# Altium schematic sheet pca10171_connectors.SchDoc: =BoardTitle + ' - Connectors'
size A3; Organization: Nordic Semiconductor; DocumentNumber: 7; SheetNumber: 7; SheetTotal: 10; CompanyName: Nordic Semiconductor; DocumentSize: A3
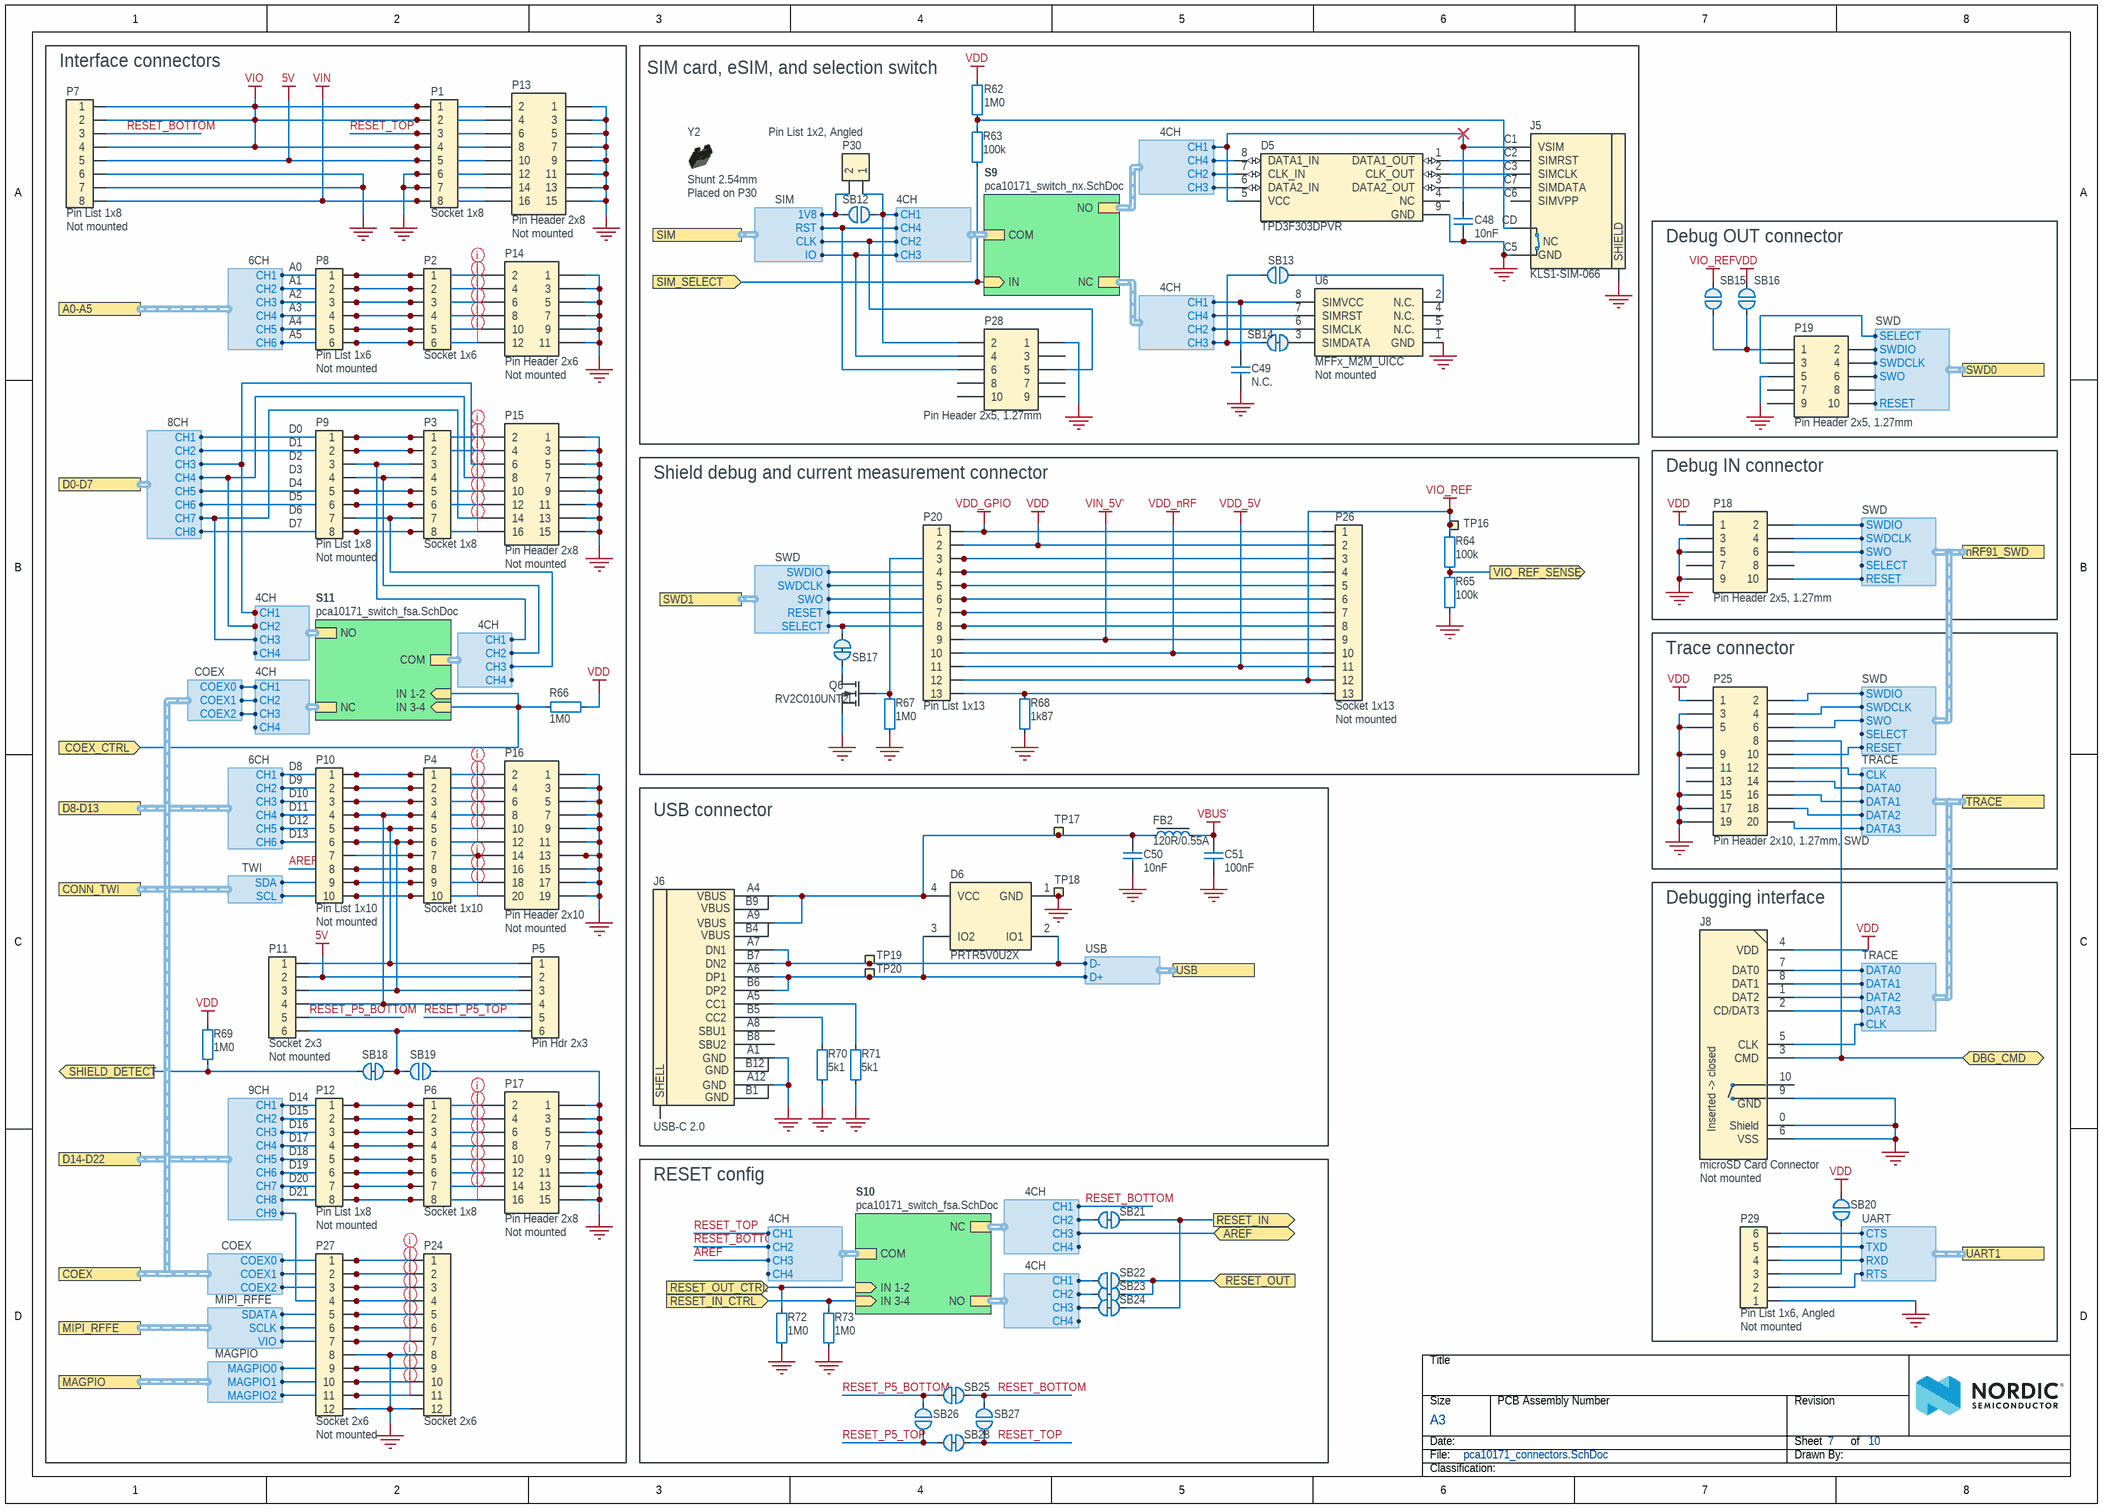
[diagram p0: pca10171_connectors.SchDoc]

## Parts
C48  10nF  [CAPC0603X03L_C]
C49  N.C.  [CAPC0603X03L_C_NC]
C50  10nF  [CAPC0603X03L_C]
C51  100nF  [CAPC0603X03L_C]
D5  TPD3F303DPVR  [SON50P210X160X65_HS-9N]
D6  PRTR5V0U2X  [SOT190P230X110-4L]
FB2  120R/0.55A  [INDC1005X04L]
J5  KLS1-SIM-066  [KLS1-SIM-066]
J6  USB-C 2.0  [SD-80259-001]
J8  microSD Card Connector  Assembly: Not mounted  [Molex_502774-0891]
P1  Socket 1x8  [SOCKET_1x8_SMD]
P2  Socket 1x6  [SOCKET_1x6_SMD]
P3  Socket 1x8  [SOCKET_1x8_SMD]
P4  Socket 1x10  [SOCKET_1x10_SMD]
P5  Pin Hdr 2x3  [HDR_2x3-SMD]
P6  Socket 1x8  [SOCKET_1x8_SMD]
P7  Pin List 1x8  Assembly: Not mounted  [LIST_1x8_SMD-NC]
P8  Pin List 1x6  Assembly: Not mounted  [LIST_1x6_SMD-NC]
P9  Pin List 1x8  Assembly: Not mounted  [LIST_1x8_SMD-NC]
P10  Pin List 1x10  Assembly: Not mounted  [LIST_1x10_SMD-NC]
P11  Socket 2x3  Assembly: Not mounted  [SOCKET_2x3_SMD-2.54mm-bottom-NC]
P12  Pin List 1x8  Assembly: Not mounted  [LIST_1x8_SMD-NC]
P13  Pin Header 2x8  Assembly: Not mounted  [HDR_2x8-NC]
P14  Pin Header 2x6  Assembly: Not mounted  [HDR_2x6-NC]
P15  Pin Header 2x8  Assembly: Not mounted  [HDR_2x8-NC]
P16  Pin Header 2x10  Assembly: Not mounted  [HDR_2x10-NC]
P17  Pin Header 2x8  Assembly: Not mounted  [HDR_2x8-NC]
P18  Pin Header 2x5, 1.27mm  [HDR_2x5-SMD-1.27mm-K]
P19  Pin Header 2x5, 1.27mm  [HDR_2x5-SMD-1.27mm-K]
P20  Pin List 1x13  [LIST_1x13_SMD]
P24  Socket 2x6  [SOCKET_2x6_SMD-2.54mm]
P25  Pin Header 2x10, 1.27mm, SWD  [HDR_2x10-SMD-1.27mm-K-SWD]
P26  Socket 1x13  Assembly: Not mounted  [LIST_1x13_SMD-NC]
P27  Socket 2x6  Assembly: Not mounted  [SOCKET_2x6_SMD-2.54mm]
P28  Pin Header 2x5, 1.27mm  [HDR_2x5-SMD-1.27mm]
P29  Pin List 1x6, Angled  Assembly: Not mounted  [LIST_ANG_1x6-SMD-2.54MM]
P30  Pin List 1x2, Angled  [LIST_ANG_1x2-SMD-2.54MM]
Q6  RV2C010UNT2L  [DFN65P100X40-3L]
R62  1M0  [RESC0603X03L_C]
R63  100k  [RESC0603X03L_C]
R64  100k  [RESC0603X03L_C]
R65  100k  [RESC0603X03L_C]
R66  1M0  [RESC0603X03L_C]
R67  1M0  [RESC0603X03L_C]
R68  1k87  [RESC0603X03L_C]
R69  1M0  [RESC0603X03L_C]
R70  5k1  [RESC0603X03L_C]
R71  5k1  [RESC0603X03L_C]
R72  1M0  [RESC0603X03L_C]
R73  1M0  [RESC0603X03L_C]
SB12  Solderbridge  [Solderbridge]  (value not drawn)  (no BOM)
SB13  Solderbridge  [Solderbridge]  (value not drawn)  (no BOM)
SB14  Solderbridge  [Solderbridge_Shorted]  (value not drawn)  (net tie, no BOM)
SB15  Solderbridge  [Solderbridge]  (value not drawn)  (no BOM)
SB16  Solderbridge  [Solderbridge]  (value not drawn)  (no BOM)
SB17  Solderbridge  [Solderbridge_Shorted]  (value not drawn)  (net tie, no BOM)
SB18  Solderbridge  [Solderbridge_Shorted]  (value not drawn)  (net tie, no BOM)
SB19  Solderbridge  [Solderbridge]  (value not drawn)  (no BOM)
SB20  Solderbridge  [Solderbridge]  (value not drawn)  (no BOM)
SB21  Solderbridge  [Solderbridge_Shorted]  (value not drawn)  (net tie, no BOM)
SB22  Solderbridge  [Solderbridge]  (value not drawn)  (no BOM)
SB23  Solderbridge  [Solderbridge_Shorted]  (value not drawn)  (net tie, no BOM)
SB24  Solderbridge  [Solderbridge_Shorted]  (value not drawn)  (net tie, no BOM)
SB25  Solderbridge  [Solderbridge_Shorted]  (value not drawn)  (net tie, no BOM)
SB26  Solderbridge  [Solderbridge]  (value not drawn)  (no BOM)
SB27  Solderbridge  [Solderbridge]  (value not drawn)  (no BOM)
SB28  Solderbridge  [Solderbridge_Shorted]  (value not drawn)  (net tie, no BOM)
TP16  Ø1.5mm,SMD  [TP_SMD_D1.5mm]  (value not drawn)  (no BOM)
TP17  Ø1.5mm,SMD  [TP_SMD_D1.5mm]  (value not drawn)  (no BOM)
TP18  Ø1.5mm,SMD  [TP_SMD_D1.5mm]  (value not drawn)  (no BOM)
TP19  Ø1.5mm,SMD  [TP_SMD_D1.5mm]  (value not drawn)  (no BOM)
TP20  Ø1.5mm,SMD  [TP_SMD_D1.5mm]  (value not drawn)  (no BOM)
U6  MFFx_M2M_UICC  Assembly: Not mounted  [SON127P600X90_HS-8N]
Y2  Shunt 2.54mm  Assembly: Placed on P30  [Shunt_2.54mm_Horizontal]

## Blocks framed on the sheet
Interface connectors: P1-P17 P24 P27 R66 R69 SB18 SB19
SIM card, eSIM, and selection switch: C48 C49 D5 J5 P28 P30 R62 R63 SB12-SB14 U6 Y2
Debug OUT connector: P19 SB15 SB16
Debug IN connector: P18
Shield debug and current measurement connector: P20 P26 Q6 R64 R65 R67 R68 SB17 TP16
Trace connector: P25
USB connector: C50 C51 D6 FB2 J6 R70 R71 TP17-TP20
Debugging interface: J8 P29 SB20
RESET config: R72 R73 SB21-SB28

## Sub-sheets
S9 = pca10171_switch_nx.SchDoc: IN (in), COM (harness 4CH), NC (harness 4CH), NO (harness 4CH)
S10 = pca10171_switch_fsa.SchDoc: IN 1-2 (in), COM (harness 4CH), NC (harness 4CH), NO (harness 4CH), IN 3-4 (in)
S11 = pca10171_switch_fsa.SchDoc: IN 1-2 (in), COM (harness 4CH), NC (harness 4CH), NO (harness 4CH), IN 3-4 (in)

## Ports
A0-A5 (harness 6CH), AREF (bidir), COEX (harness COEX), COEX_CTRL (in), CONN_TWI (harness TWI), D0-D7 (harness 8CH), D8-D13 (harness 6CH), D14-D22 (harness 9CH), DBG_CMD (bidir), MAGPIO (harness MAGPIO), MIPI_RFFE (harness MIPI_RFFE), nRF91_SWD (harness SWD), RESET_IN (out), RESET_IN_CTRL (in), RESET_OUT (in), RESET_OUT_CTRL (in), SHIELD_DETECT (out), SIM (harness SIM), SIM_SELECT (in), SWD0 (harness SWD), SWD1 (harness SWD), TRACE (harness TRACE), UART1 (harness UART), USB (harness USB), VIO_REF_SENSE (out)

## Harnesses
SWD: SWDIO, SWDCLK, SWO, RESET, SELECT
6CH: CH1, CH2, CH3, CH4, CH5, CH6
8CH: CH1, CH2, CH3, CH4, CH5, CH6, CH7, CH8
COEX: COEX0, COEX2, COEX1
TRACE: CLK, DATA0, DATA1, DATA3, DATA2
USB: D+, D-
UART: RTS, CTS, RXD, TXD
MIPI_RFFE: SDATA, VIO, SCLK
MAGPIO: MAGPIO0, MAGPIO2, MAGPIO1
TWI: SCL, SDA
9CH: CH1, CH2, CH3, CH4, CH5, CH6, CH7, CH8, CH9
4CH: CH1, CH2, CH3, CH4
SIM: CLK, IO, 1V8, RST

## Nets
5V: P1.5 P5.2 P7.5 P11.2 P13.10
GND: C48.2 C49.1 C50.1 C51.1 D5.9(GND) D6.1(GND) J5.0(SHIELD) J5.C5(GND) J6.A1(GND) J6.A12(GND) J8.0(Shield) J8.6(VSS) J8.9 P1.6 P1.7 P4.7 P7.6 P7.7 P10.7 P13.1 P13.3 P13.5 P13.7 P13.9 P13.11 P13.12 P13.13 P13.14 P13.15 P14.1 P14.3 P14.5 P14.7 P14.9 P14.11 P15.1 P15.3 P15.5 P15.7 P15.9 P15.11 P15.13 P15.15 P16.1 P16.3 P16.5 P16.7 P16.9 P16.11 P16.13 P16.14 P16.15 P16.17 P16.19 P17.1 P17.3 P17.5 P17.7 P17.9 P17.11 P17.13 P17.15 P18.3 P18.5 P18.9 P19.5 P24.8 P24.12 P25.3 P25.5 P25.9 P25.15 P25.17 P25.19 P27.8 P27.12 P28.1 P29.1 Q6.2(S) R65.1 R67.2 R68.1 R70.1 R71.1 R72.2 R73.1 SB19.1 TP18.1 U6.1(GND)
VBUS': C51.2 FB2.2
VDD: J8.4(VDD) P18.1 P20.2 P25.1 P26.2 R62.1 R66.1 R69.2 SB16.2 SB20.1
VDD_5V: P20.11 P26.11
VDD_GPIO: P20.1 P26.1
VDD_nRF: P20.10 P26.10
VIN: P1.8 P7.8 P13.16
VIN_5V': P20.9 P26.9
VIO: P1.1 P1.2 P1.4 P7.1 P7.2 P7.4 P13.2 P13.4 P13.8
VIO_REF: P20.12 P26.12 R64.1 SB15.2 TP16.1
AREF: P4.8 P10.8 P16.16 ; sheet S10/COM.CH3
AREF: port AREF, sheet S10/NC.CH3  [a separate net that carries the same name]
COEX_CTRL: R66.2 ; port COEX_CTRL, sheet S11/IN 1-2, sheet S11/IN 3-4
DBG_CMD: J8.3(CMD) P25.8 ; port DBG_CMD
RESET_BOTTOM: P7.3 SB25.1 SB27.1 ; sheet S10/NC.CH1, sheet S10/COM.CH2
RESET_IN: SB21.2 SB24.2 ; port RESET_IN
RESET_IN_CTRL: R73.2 ; port RESET_IN_CTRL, sheet S10/IN 3-4
RESET_OUT: SB22.1 SB23.1 ; port RESET_OUT
RESET_OUT_CTRL: R72.1 ; port RESET_OUT_CTRL, sheet S10/IN 1-2
RESET_P5_BOTTOM: P11.5 SB25.2 SB26.2
RESET_P5_TOP: P5.5 SB26.1 SB28.2
RESET_TOP: P1.3 P13.6 SB27.2 SB28.1 ; sheet S10/COM.CH1
SHIELD_DETECT: R69.1 SB18.2 ; port SHIELD_DETECT
SIM_SELECT: R63.1 ; port SIM_SELECT, sheet S9/IN
VIO_REF_SENSE: R64.2 R65.2 ; port VIO_REF_SENSE
NetC48_1: C48.1 D5.5(VCC) J5.C1(VSIM) ; sheet S9/NO.CH1
NetC49_2: C49.2 U6.8(SIMVCC) ; sheet S9/NC.CH1
NetC50_2: C50.2 D6.4(VCC) FB2.1 J6.A4(VBUS) J6.A9(VBUS) TP17.1
NetD5_1: D5.1(DATA1_OUT) J5.C2(SIMRST)
NetD5_2: D5.2(CLK_OUT) J5.C3(SIMCLK)
NetD5_3: D5.3(DATA2_OUT) J5.C7(SIMDATA)
NetD5_6: D5.6(DATA2_IN) ; sheet S9/NO.CH3
NetD5_7: D5.7(CLK_IN) ; sheet S9/NO.CH2
NetD5_8: D5.8(DATA1_IN) ; sheet S9/NO.CH4
NetD6_2: D6.2(IO1) J6.A7(DN1) J6.B7(DN2) TP19.1 ; port USB.D-
NetD6_3: D6.3(IO2) J6.A6(DP1) J6.B6(DP2) TP20.1 ; port USB.D+
NetJ5_CD: J5.CD R62.2 R63.2
NetJ6_A5: J6.A5(CC1) R71.2
NetJ6_B5: J6.B5(CC2) R70.2
NetJ8_1: J8.1(DAT2) P25.18 ; port TRACE.DATA2
NetJ8_2: J8.2(CD/DAT3) P25.20 ; port TRACE.DATA3
NetJ8_5: J8.5(CLK) P25.12 ; port TRACE.CLK
NetJ8_7: J8.7(DAT0) P25.14 ; port TRACE.DATA0
NetJ8_8: J8.8(DAT1) P25.16 ; port TRACE.DATA1
NetP2_1: P2.1 P8.1 P14.2 ; port A0-A5.CH1
NetP2_2: P2.2 P8.2 P14.4 ; port A0-A5.CH2
NetP2_3: P2.3 P8.3 P14.6 ; port A0-A5.CH3
NetP2_4: P2.4 P8.4 P14.8 ; port A0-A5.CH4
NetP2_5: P2.5 P8.5 P14.10 ; port A0-A5.CH5
NetP2_6: P2.6 P8.6 P14.12 ; port A0-A5.CH6
NetP3_1: P3.1 P9.1 P15.2 ; port D0-D7.CH1
NetP3_2: P3.2 P9.2 P15.4 ; port D0-D7.CH2
NetP3_3: P3.3 P9.3 ; sheet S11/COM.CH1
NetP3_4: P3.4 P9.4 ; sheet S11/COM.CH2
NetP3_5: P3.5 P9.5 P15.10 ; port D0-D7.CH5
NetP3_6: P3.6 P9.6 P15.12 ; port D0-D7.CH6
NetP3_7: P3.7 P9.7 ; sheet S11/COM.CH3
NetP3_8: P3.8 P9.8 P15.16 ; port D0-D7.CH8
NetP4_1: P4.1 P10.1 P16.2 ; port D8-D13.CH1
NetP4_2: P4.2 P10.2 P16.4 ; port D8-D13.CH2
NetP4_3: P4.3 P10.3 P16.6 ; port D8-D13.CH3
NetP4_4: P4.4 P5.4 P10.4 P11.4 P16.8 ; port D8-D13.CH4
NetP4_5: P4.5 P5.1 P10.5 P11.1 P16.10 ; port D8-D13.CH5
NetP4_6: P4.6 P5.3 P10.6 P11.3 P16.12 ; port D8-D13.CH6
NetP4_9: P4.9 P10.9 P16.18 ; port CONN_TWI.SDA
NetP4_10: P4.10 P10.10 P16.20 ; port CONN_TWI.SCL
NetP5_6: P5.6 P11.6 SB18.1 SB19.2
NetP6_1: P6.1 P12.1 P17.2 ; port D14-D22.CH1
NetP6_2: P6.2 P12.2 P17.4 ; port D14-D22.CH2
NetP6_3: P6.3 P12.3 P17.6 ; port D14-D22.CH3
NetP6_4: P6.4 P12.4 P17.8 ; port D14-D22.CH4
NetP6_5: P6.5 P12.5 P17.10 ; port D14-D22.CH5
NetP6_6: P6.6 P12.6 P17.12 ; port D14-D22.CH6
NetP6_7: P6.7 P12.7 P17.14 ; port D14-D22.CH7
NetP6_8: P6.8 P12.8 P17.16 ; port D14-D22.CH8
NetP15_6: P15.6 ; port D0-D7.CH3, sheet S11/NO.CH1
NetP15_8: P15.8 ; port D0-D7.CH4, sheet S11/NO.CH2
NetP15_14: P15.14 ; port D0-D7.CH7, sheet S11/NO.CH3
NetP18_2: P18.2 P25.2 ; port nRF91_SWD.SWDIO
NetP18_4: P18.4 P25.4 ; port nRF91_SWD.SWDCLK
NetP18_6: P18.6 P25.6 ; port nRF91_SWD.SWO
NetP18_10: P18.10 P25.10 ; port nRF91_SWD.RESET
NetP19_1: P19.1 SB15.1 SB16.1
NetP19_2: P19.2 ; port SWD0.SWDIO
NetP19_3: P19.3 ; port SWD0.SELECT
NetP19_4: P19.4 ; port SWD0.SWDCLK
NetP19_6: P19.6 ; port SWD0.SWO
NetP19_10: P19.10 ; port SWD0.RESET
NetP20_3: P20.3 P26.3 Q6.1(G) R67.1
NetP20_4: P20.4 P26.4 ; port SWD1.SWDIO
NetP20_5: P20.5 P26.5 ; port SWD1.SWDCLK
NetP20_6: P20.6 P26.6 ; port SWD1.SWO
NetP20_7: P20.7 P26.7 ; port SWD1.RESET
NetP20_8: P20.8 P26.8 SB17.2 ; port SWD1.SELECT
NetP20_13: P20.13 P26.13 R68.2
NetP24_1: P24.1 P27.1 ; port COEX.COEX0, sheet S11/NC.CH1
NetP24_2: P24.2 P27.2 ; port COEX.COEX1, sheet S11/NC.CH2
NetP24_3: P24.3 P27.3 ; port COEX.COEX2, sheet S11/NC.CH3
NetP24_4: P24.4 P27.4 ; port D14-D22.CH9
NetP24_5: P24.5 P27.5 ; port MIPI_RFFE.SDATA
NetP24_6: P24.6 P27.6 ; port MIPI_RFFE.SCLK
NetP24_7: P24.7 P27.7 ; port MIPI_RFFE.VIO
NetP24_9: P24.9 P27.9 ; port MAGPIO.MAGPIO0
NetP24_10: P24.10 P27.10 ; port MAGPIO.MAGPIO1
NetP24_11: P24.11 P27.11 ; port MAGPIO.MAGPIO2
NetP28_2: P28.2 P30.1 SB12.2 ; sheet S9/COM.CH1
NetP28_4: P28.4 ; sheet S9/COM.CH3, port SIM.IO
NetP28_5: P28.5 ; sheet S9/COM.CH2, port SIM.CLK
NetP28_6: P28.6 ; sheet S9/COM.CH4, port SIM.RST
NetP29_2: P29.2 ; port UART1.RTS
NetP29_3: P29.3 SB20.2
NetP29_4: P29.4 ; port UART1.RXD
NetP29_5: P29.5 ; port UART1.TXD
NetP29_6: P29.6 ; port UART1.CTS
NetP30_2: P30.2 SB12.1 ; port SIM.1V8
NetQ6_3: Q6.3(D) SB17.1
NetSB13_1: SB13.1 U6.2(N.C.)
NetSB13_2: SB13.2 SB14.2 ; sheet S9/NC.CH3
NetSB14_1: SB14.1 U6.3(SIMDATA)
NetSB21_1: SB21.1 ; sheet S10/NC.CH2
NetSB22_2: SB22.2 ; sheet S10/NO.CH1
NetSB23_2: SB23.2 ; sheet S10/NO.CH2
NetSB24_1: SB24.1 ; sheet S10/NO.CH3
NetU6_6: U6.6(SIMCLK) ; sheet S9/NC.CH2
NetU6_7: U6.7(SIMRST) ; sheet S9/NC.CH4

Not connected (* = marked no-connect by the designer): D5 4(NC); J5 C6(SIMVPP); J6 A8(SBU1) B8(SBU2) SHLD(SHELL); J8 10; P18 7 8; P19 7 8 9; P25 11 13; P28 3 7 8 9 10; U6 4(N.C.) 5(N.C.)

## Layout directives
net class GPIO: AREF, NetP2_1, NetP2_2, NetP2_3, NetP2_4, NetP2_5, NetP2_6, NetP3_1, NetP3_2, NetP3_5, NetP3_6, NetP3_8, NetP4_1, NetP4_2, NetP4_3, NetP4_4, NetP4_5, NetP4_6, NetP4_9, NetP4_10, NetP6_1, NetP6_2, NetP6_3, NetP6_4, NetP6_5, NetP6_6, NetP6_7, NetP6_8, NetP15_6, NetP15_8, NetP15_14, NetP24_1, NetP24_2, NetP24_3, NetP24_4, NetP24_5, NetP24_6, NetP24_7, NetP24_9, NetP24_10, NetP24_11

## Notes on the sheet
- (near P8) A0
- (near P8) A1
- (near P8) A2
- (near P8) A3
- (near P8) A4
- (near P8) A5
- (near P9) D0
- (near P9) D1
- (near P9) D2
- (near P9) D3
- (near P9) D4
- (near P9) D5
- (near P9) D6
- (near P9) D7
- (near P10) D8
- (near P10) D9
- (near P10) D10
- (near P10) D11
- (near P10) D12
- (near P10) D13
- (near P12) D14
- (near P12) D15
- (near P12) D16
- (near P12) D17
- (near P12) D18
- (near P12) D19
- (near P12) D20
- (near P12) D21

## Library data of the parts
C48 C50 = C0201-10n: Capacitor, X7R, ±10%; Manufacturer: N.A.; Part number IPS: 00000003480; Part number Norautron: 26621779; Part number NEMS: 100200067; Note: 10V; Pad Count: 2; Component Status: Active
C49 = C0201-N.C.: Not mounted; Manufacturer: N.A.; Part number NEMS: 100200001; Note: Chip Cap; Assembly: Not mounted; Pad Count: 2; Component Status: Active
C51 = C0201-100n: Capacitor, X5R, ±10%; Manufacturer: N.A.; Part number IPS: 00000001248, 00000002505; Part number Norautron: 262071862; Part number NEMS: 100200078; Note: 16V; Pad Count: 2; Component Status: Active
D5 = TPD3F303DPVR: ESD Protection and EMI Filter for SIM Card Interface; Manufacturer: Texas Instruments; Part number NEMS: 101900729; Note: N.A.; Pad Count: 8; Component Status: Active
D6 = PRTR5V0U2X: Ultra low capacitance double rail-to-rail ESD protection diode; Manufacturer: NXP Semiconductors; Part number IPS: 00000009951; Part number Norautron: 26313940; Part number NEMS: 101300082; Note: N.A.; Artikkelnr Noca: 10069015; Pad Count: 4; Component Status: Active
FB2 = FB0402-120R@100M-500mA: Ferrite Bead, 120 Ohm @ 100MHz, 500mA, 250 mOhm Max; Manufacturer: Murata; Manufacturer Part Number: BLM15AG121SN1D; Part number IPS: 00000009954; Part number Norautron: 265230631; Part number NEMS: 100300099; Note: Chip EMIFIL Inductor Type Chip Ferrite Bead; Artikkelnr Noca: 33029317; Pad Count: 2; Component Status: Active
J5 = L-KLS1-SIM-066-(6+1)P-H1.37-R: Nano SIM Card Connector, Push-Push, 6-Pin, H1.37mm, with CD Pin; Manufacturer: KLS Electronic; Part number NEMS: 100500776; Note: N.A.; Pad Count: 7; Component Status: Active
J6 = 80259-1021: USB-C Receptacle, 16 Pin, USB 2.0; Manufacturer: Bellweather Electronic Corp.; Part number NEMS: 100500830; Component Status: Active; Pad Count: 16; Note: N.A.; System: Connector
J8 = Molex_502774-0891: 1.10mm Pitch microSD Memory Card Connector, Reverse Mount Surface Mount, Push-Push Type; Manufacturer: Molex; Part number IPS: 00000001284; Part number NEMS: 100500509; Note: N.A.; Pad Count: 14; Component Status: Active
P1 P3 P6 = Socket 1x8 SMD: Socket 1x8, 2.54mm (100mil), SMD; Manufacturer: WCON; Manufacturer Part Number: 2171-108MS0CUNR1; Part number IPS: 00000009963; Part number Norautron: 26032369; Part number NEMS: 100500412; Note: N.A.; Artikkelnr Noca: 55030002; Pad Count: 8; Component Status: Active; System: Connector
P2 = Socket 1x6 SMD: Socket 1x6, 2.54mm (100mil), SMD; Manufacturer: WCON; Manufacturer Part Number: 2171-106MS0CUNR1; Part number IPS: 00000009964; Part number Norautron: 26032370; Part number NEMS: 100500408; Note: N.A.; Artikkelnr Noca: 55030001; Pad Count: 6; Component Status: Active; System: Connector
P4 = Socket 1x10 SMD: Socket 1x10, 2.54mm (100mil), SMD; Manufacturer: WCON; Manufacturer Part Number: 2171-110MS0CUNR1; Part number IPS: 00000009965; Part number Norautron: 26032371; Part number NEMS: 100500416; Note: N.A.; Artikkelnr Noca: 55030004; Pad Count: 10; Component Status: Active; System: Connector
P5 = Pin Header 2x3 SMD: Pin Header 2x3, 2.54mm (100mil) SMD; Manufacturer: WCON; Manufacturer Part Number: 1125-1203S0M116R1; Part number IPS: 00000009966; Part number Norautron: N.A.; Part number NEMS: 100500242; Artikkelnr Noca: 55010007; Pad Count: 6; Component Status: Active; System: Connector
P7 P9 P12 = Pin List 1x8 SMD, N.C.: Pin List 1x8, 2.54mm (100mil), SMD; Manufacturer: WCON; Manufacturer Part Number: 1125-1108S0M116R2; Part number NEMS: 100500330; Note: N.A.; Artikkelnr Noca: 55010006; Pad Count: 8; Component Status: Active; System: Connector
P8 = Pin List 1x6 SMD, N.C.: Pin List 1x6, 2.54mm (100mil), SMD; Manufacturer: WCON; Manufacturer Part Number: 1125-1106S0M116R2; Part number NEMS: 100500321; Note: N.A.; Artikkelnr Noca: 55010026; Pad Count: 6; Component Status: Active; System: Connector
P10 = Pin List 1x10 SMD, N.C.: Pin List 1x10, 2.54mm (100mil), SMD; Manufacturer: WCON; Manufacturer Part Number: 1125-1110S0M116R2; Part number NEMS: 100500338; Note: N.A.; Artikkelnr Noca: 55010028; Pad Count: 10; Component Status: Active; System: Connector
P11 = Socket 2x3 SMD Bottom, N.C.: Socket 2x3, 2.54mm (100mil), SMD; Manufacturer: WCON; Manufacturer Part Number: 2171-203MS0CUNR1; Part number NEMS: 100500434; Note: N.A.; Artikkelnr Noca: 55030010; Pad Count: 6; Component Status: Active; System: Connector
P13 P15 P17 = Pin Header 2x8, N.C.: Pin Header 2x8, 2.54mm (100mil); Manufacturer: N.A.; Part number NEMS: 100500270; Pad Count: 16; Component Status: Active; System: Connector
P14 = Pin Header 2x6, N.C.: Pin Header 2x6, 2.54mm (100mil); Manufacturer: N.A.; Part number NEMS: 100500265; Pad Count: 12; Component Status: Active; System: Connector
P16 = Pin Header 2x10, N.C.: Pin Header 2x10, 2.54mm (100mil); Manufacturer: N.A.; Part number NEMS: 100500274; Pad Count: 20; Component Status: Active; System: Connector
P18 P19 = Pin Header 2x5 SMD, 1.27mm, KS: Pin Header 2x5, 1.27mm (50mil), SMD, Keying Shroud; Manufacturer: WCON; Manufacturer Part Number: 3132-10MS0BK00R1; Part number IPS: 00000009968; Part number NEMS: 100500261; Note: N.A.; Artikkelnr Noca: 55010009; Pad Count: 10; Component Status: Active; System: Connector
P20 = Pin List 1x13 SMD: Pin List 1x13, 2.54mm (100mil), SMD; Manufacturer: N.A.; Part number IPS: 00000002499; Part number NEMS: 100500345; Pad Count: 13; Component Status: Active; System: Connector
P24 P27 = Socket 2x6 SMD: Socket 2x6, 2.54mm (100mil), SMD; Manufacturer: WCON; Manufacturer Part Number: 2171-206MS0CUNR1; Part number NEMS: 100500439; Note: N.A.; Pad Count: 12; Component Status: Active; System: Connector
P25 = Pin Header 2x10 SMD, 1.27mm, KS, SWD (Cabcon): Pin Header 2x10, 1.27mm (50mil), SMD, Keying Shroud, Removed Pin 7; Manufacturer: WCON; Manufacturer Part Number: 3132-20MS0BK00R3; Part number NEMS: 100500841,100500280; Note: N.A.; Pad Count: 19; Component Status: Active; System: Connector
P26 = Socket 1x13 SMD, N.C.: Socket 1x13, 2.54mm (100mil), SMD; Manufacturer: WCON; Manufacturer Part Number: 2171-113MS0CUNR1; Part number NEMS: 100500422; Note: N.A.; Pad Count: 13; Component Status: Active; System: Connector
P28 = Pin Header 2x5 SMD, 1.27mm: Pin Header 2x5, 1.27mm (50mil), SMD; Manufacturer: WCON; Manufacturer Part Number: 1325-1205S0M078R1; Part number IPS: 00000009970; Part number NEMS: 100500259; Note: N.A.; Artikkelnr Noca: 55019196; Pad Count: 10; Component Status: Active; System: Connector
P29 = Pin List Ang 1x6 SMD, 2.54mm: Pin List 1x6, 2.54mm (100mil), Right Angled, SMD; Manufacturer: N.A.; Part number IPS: 00000003922; Part number NEMS: 100500362; Pad Count: 6; Component Status: Active; System: Connector
P30 = Pin List Ang 1x2 SMD, 2.54mm: Pin List 1x2, 2.54mm (100mil), Right Angled, SMD; Manufacturer: WCON; Manufacturer Part Number: 1125B-1102S0Z135R2; Part number IPS: 00000009972; Part number NEMS: 100500354; Note: N.A.; Artikkelnr Noca: 55010023; Pad Count: 2; Component Status: Active; System: Connector
Q6 = RV2C010UNT2L: N-Channel MOSFET, 20V, 1A, 470mOhm, 400mW; Manufacturer: Rohm Semiconductor; Part number IPS: 00000009976; Part number Norautron: 26320026; Part number NEMS: 101300132; Note: N.A.; Artikkelnr Noca: 35010020; Pad Count: 3; Component Status: Active
R62 R66 R67 R69 R72 R73 = R0201-1M0: Resistor, ±1%, 0.05W; Manufacturer: N.A.; Part number IPS: 00000001418; Part number Norautron: 26107108; Part number NEMS: 100100093; Note: Chip Res 1%; Pad Count: 2; Component Status: Active
R63-R65 = R0201-100k: Resistor, ±1%, 0.05W; Manufacturer: N.A.; Part number IPS: 00000001419; Part number Norautron: 26108487; Part number NEMS: 100100080; Note: Chip Res 1%; Pad Count: 2; Component Status: Active
R68 = R0201-1k87: Resistor, ±1%, 0.05W; Manufacturer: N.A.; Part number NEMS: 100100050; Note: Chip Res 1%; Pad Count: 2; Component Status: Active
R70 R71 = R0201-5k1: Resistor, ±1%, 0.05W; Manufacturer: N.A.; Part number Norautron: 26192285; Part number NEMS: 100100565; Pad Count: 2; Note: Chip Res 1%; Component Status: Active
SB12 SB13 SB15 SB16 SB19 SB20 SB22 SB26 SB27 = Solderbridge: Manufacturer: N.A.; Part number NEMS: 100500458; Pad Count: 2; Component Status: Active; System: Connector
SB14 SB18 SB21 SB23-SB25 SB28 = Solderbridge Shorted: Shorted Solderbridge; Manufacturer: N.A.; Part number NEMS: 100500459; Pad Count: 2; Component Status: Active; System: Connector
SB17 = Solderbridge Shorted: Shorted Solderbridge; Manufacturer: N.A.; Part number NEMS: 100500459; Component Status: Active; Pad Count: 2; System: Connector
TP16-TP20 = TP_SMD_Ø1.5MM: 1.5mm circular SMD testpad; Manufacturer: Nordic Semiconductor; Manufacturer Part Number: N.A.; Part number NEMS: 100500477; Pad Count: 1; Component Status: Active
U6 = M2M_UICC: M2M UICC SIM Card; Manufacturer: N.A.; Part number NEMS: 101900595; Pad Count: 8; Component Status: Active
Y2 = SHUNT JUMPER 2.54mm BLACK GOLD Horizontal (obsolete): Shunt Jumper 2.54mm Black; Manufacturer: 3M; Manufacturer Part Number: 969102-0000-DA; Part number IPS: 00000001916; Part number Norautron: N.A.; Part number NEMS: 100500644; Note: SHUNT JUMPER .1" BLACK GOLD, h=6.00mm, w=5.00mm; Artikkelnr Noca: 56099001; Pad Count: 2; System: Connector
